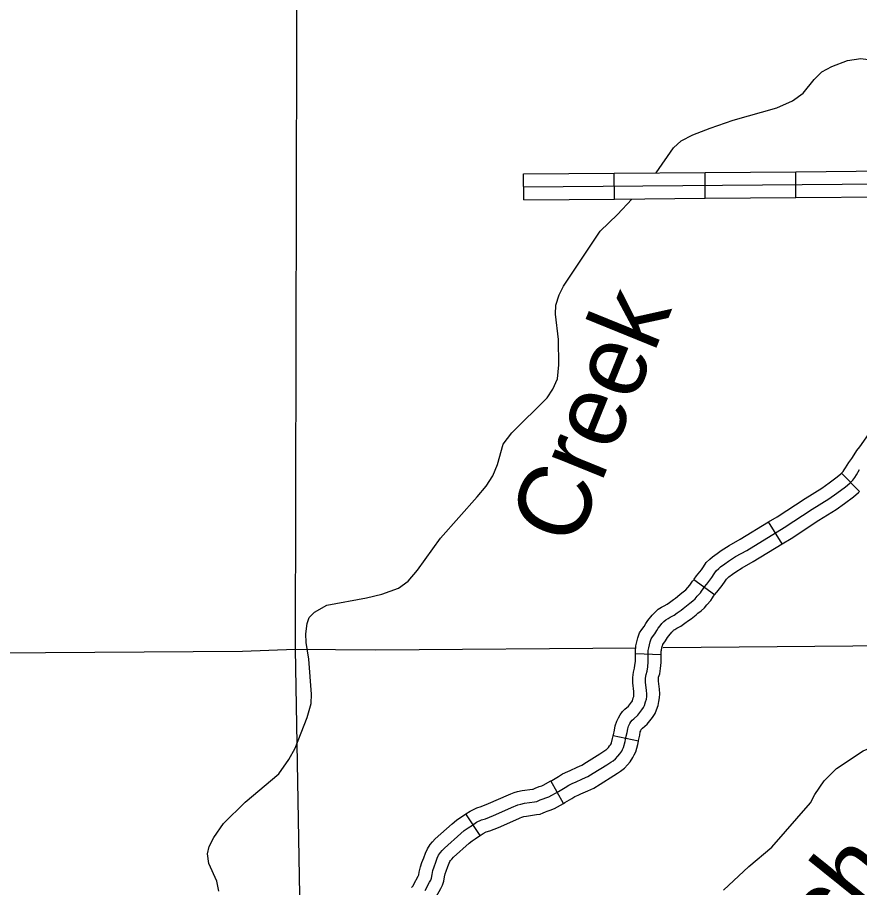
# Model space of a CAD drawing. Extents: x 1377389 to 1380723, y 1168351 to 1170484.
# Drawn here: x 1379286.7 to 1379384.7, y 1168808.8 to 1168910 of the extents above; entities that cross this region are included whole.
import ezdxf

# ---------------------------------------------------------------- set-up
doc = ezdxf.new("R2010")
doc.units = 0
doc.layers.add('B_Fill', color=7, linetype='Continuous')

msp = doc.modelspace()

# ---------------------------------------------------------------- linework, layer by layer
at = {"layer": 'B_Fill'}
for p, q in [((1379345.66, 1168888.81), (1379345.64, 1168891.81)), ((1379356.22, 1168888.89), (1379356.2, 1168891.89)), ((1379366.78, 1168888.98), (1379366.76, 1168891.98)), ((1379377.34, 1168889.07), (1379377.32, 1168892.07)), ((1379384.75, 1168854.89), (1379382.62, 1168857.01)), ((1379375.72, 1168848.78), (1379374.16, 1168851.34)), ((1379367.87, 1168842.86), (1379365.44, 1168844.62)), ((1379361.65, 1168835.89), (1379358.66, 1168836.01)), ((1379359, 1168825.85), (1379356.07, 1168826.46)), ((1379350.27, 1168818.59), (1379348.81, 1168821.21)), ((1379340.6, 1168814.88), (1379338.93, 1168817.37))]:
    msp.add_line(p, q, dxfattribs=at)
for points in [[(1379319.28, 1168942.2), (1379319.08, 1168836.54)], [(1379361.06, 1168891.95), (1379363.09, 1168894.85), (1379363.99, 1168895.67), (1379365.34, 1168896.37), (1379367.35, 1168897.12), (1379370.04, 1168898.06), (1379375.13, 1168899.52), (1379376.94, 1168900.3), (1379378.18, 1168901.2), (1379379.45, 1168902.78), (1379380.37, 1168903.7), (1379381.5, 1168904.33), (1379383.33, 1168905.01), (1379384.87, 1168905.24), (1379386.34, 1168905.04), (1379387.69, 1168905.62), (1379390.71, 1168908.37)], [(1379377.32, 1168892.07), (1379387.88, 1168892.16)], [(1379345.64, 1168891.81), (1379356.2, 1168891.89)], [(1379356.2, 1168891.89), (1379366.76, 1168891.98)], [(1379366.76, 1168891.98), (1379377.32, 1168892.07)], [(1379345.65, 1168890.31), (1379415.15, 1168890.89)], [(1379377.34, 1168889.07), (1379387.9, 1168889.16)], [(1379345.66, 1168888.81), (1379356.22, 1168888.89)], [(1379349.04, 1168866.78), (1379349.59, 1168868), (1379349.76, 1168869.6), (1379349.69, 1168872.54), (1379349.36, 1168875.49), (1379349.41, 1168876.56), (1379349.78, 1168877.75), (1379350.28, 1168878.78), (1379354.57, 1168885.14), (1379356.59, 1168887.09), (1379358.25, 1168888.89)], [(1379356.22, 1168888.89), (1379366.78, 1168888.98)], [(1379366.78, 1168888.98), (1379377.34, 1168889.07)], [(1379310.17, 1168808.39), (1379309.96, 1168809.57), (1379309.01, 1168811.61), (1379308.88, 1168812.73), (1379309.04, 1168813.58), (1379309.58, 1168814.62), (1379310.73, 1168816.25), (1379313.25, 1168818.73), (1379317.15, 1168822.05), (1379318.33, 1168823.7), (1379319.05, 1168825.02), (1379320.46, 1168828.59), (1379320.92, 1168830.23), (1379320.96, 1168831.29), (1379320.66, 1168835.37), (1379320.36, 1168837.3), (1379320.31, 1168838.34), (1379320.46, 1168839.53), (1379320.69, 1168840.22), (1379321.3, 1168840.85), (1379322.75, 1168841.64), (1379327.38, 1168842.5), (1379329.14, 1168842.92), (1379331.09, 1168843.62), (1379332.23, 1168844.45), (1379333.3, 1168845.72), (1379335.97, 1168849.45), (1379340.26, 1168854.25), (1379341.28, 1168855.51), (1379342.07, 1168856.71), (1379342.61, 1168858.02), (1379343.27, 1168860.37), (1379344.27, 1168861.72), (1379348.37, 1168865.77), (1379349.04, 1168866.78)], [(1379382.62, 1168857.01), (1379382.82, 1168857.21), (1379382.96, 1168857.38), (1379383.11, 1168857.63), (1379383.51, 1168858.26), (1379383.84, 1168858.72), (1379384.13, 1168859.16), (1379384.44, 1168859.63), (1379384.78, 1168860.07), (1379387.06, 1168863.34), (1379388.44, 1168865.44)], [(1379361.15, 1168838.72), (1379361.32, 1168838.98), (1379361.54, 1168839.25), (1379361.75, 1168839.51), (1379361.98, 1168839.75), (1379362.2, 1168839.97), (1379362.47, 1168840.11), (1379362.72, 1168840.27), (1379363.15, 1168840.49), (1379363.51, 1168840.76), (1379363.97, 1168841.09), (1379364.23, 1168841.28), (1379364.78, 1168841.72), (1379365, 1168841.9), (1379365.35, 1168842.16), (1379365.61, 1168842.41), (1379365.86, 1168842.69), (1379366.22, 1168843.08), (1379366.34, 1168843.3), (1379366.53, 1168843.56), (1379366.69, 1168843.79), (1379366.95, 1168844.11), (1379367.54, 1168844.86), (1379367.84, 1168845.29), (1379368.07, 1168845.65), (1379368.35, 1168845.92), (1379368.57, 1168846.12), (1379369.06, 1168846.47), (1379369.49, 1168846.79), (1379370.32, 1168847.3), (1379371.61, 1168848.03), (1379375.97, 1168850.69), (1379379.22, 1168852.82), (1379381.18, 1168854.01), (1379382.1, 1168854.68), (1379383.09, 1168855.41), (1379383.6, 1168855.86), (1379383.94, 1168856.21), (1379384.18, 1168856.51), (1379384.39, 1168856.83), (1379384.75, 1168857.42)], [(1379374.16, 1168851.34), (1379375.17, 1168851.95), (1379378.41, 1168854.08), (1379380.35, 1168855.26), (1379381.21, 1168855.89), (1379382.15, 1168856.58), (1379382.57, 1168856.95), (1379382.62, 1168857.01)], [(1379375.72, 1168848.78), (1379376.78, 1168849.42), (1379380.02, 1168851.55), (1379382.02, 1168852.77), (1379382.98, 1168853.47), (1379384.03, 1168854.24), (1379384.62, 1168854.77), (1379384.75, 1168854.89)], [(1379365.44, 1168844.62), (1379365.5, 1168844.7), (1379365.78, 1168845.05), (1379366.34, 1168845.76), (1379366.59, 1168846.12), (1379366.89, 1168846.61), (1379367.33, 1168847.02), (1379367.63, 1168847.29), (1379368.17, 1168847.67), (1379368.64, 1168848.03), (1379369.56, 1168848.59), (1379370.86, 1168849.32), (1379374.16, 1168851.34)], [(1379367.87, 1168842.86), (1379367.88, 1168842.87), (1379368.12, 1168843.18), (1379368.74, 1168843.96), (1379369.1, 1168844.46), (1379369.24, 1168844.7), (1379369.37, 1168844.81), (1379369.51, 1168844.95), (1379369.95, 1168845.26), (1379370.33, 1168845.55), (1379371.08, 1168846), (1379372.37, 1168846.73), (1379375.72, 1168848.78)], [(1379358.66, 1168836.01), (1379358.66, 1168836.06), (1379358.66, 1168836.5), (1379358.72, 1168836.94), (1379358.82, 1168837.4), (1379358.94, 1168837.86), (1379359.15, 1168838.44), (1379359.42, 1168838.83), (1379359.66, 1168839.16), (1379359.88, 1168839.53), (1379360.11, 1168839.87), (1379360.62, 1168840.5), (1379360.92, 1168840.81), (1379361.31, 1168841.19), (1379361.71, 1168841.41), (1379361.99, 1168841.58), (1379362.36, 1168841.77), (1379362.62, 1168841.96), (1379363.09, 1168842.31), (1379363.33, 1168842.48), (1379363.84, 1168842.88), (1379364.07, 1168843.08), (1379364.38, 1168843.31), (1379364.53, 1168843.45), (1379364.74, 1168843.7), (1379365, 1168843.97), (1379365.06, 1168844.09), (1379365.3, 1168844.43), (1379365.44, 1168844.62)], [(1379368.91, 1168808.52), (1379371.87, 1168811.26), (1379374.55, 1168813.52), (1379379.02, 1168818.66), (1379379.55, 1168819.63), (1379380.64, 1168821.22), (1379382.06, 1168822.67), (1379385.15, 1168824.71), (1379387.5, 1168825.69), (1379389.38, 1168826.09), (1379395.47, 1168825.84), (1379400.06, 1168825.42), (1379401.05, 1168825.58), (1379401.74, 1168825.89), (1379402.06, 1168826.26), (1379402.69, 1168827.8), (1379403.18, 1168830.02), (1379403.74, 1168831.65), (1379404.6, 1168833.21), (1379406.14, 1168834.84), (1379408.31, 1168836.36), (1379416.83, 1168840.28), (1379419.61, 1168841.74), (1379421.82, 1168843.62)], [(1379361.65, 1168835.89), (1379361.66, 1168836.01), (1379361.66, 1168836.29), (1379361.68, 1168836.41), (1379361.74, 1168836.71), (1379361.81, 1168836.97), (1379361.84, 1168837.06), (1379361.86, 1168837.09), (1379362.16, 1168837.49), (1379362.41, 1168837.91), (1379362.53, 1168838.09), (1379362.88, 1168838.53), (1379363.04, 1168838.69), (1379363.09, 1168838.75), (1379363.23, 1168838.82), (1379363.46, 1168838.97), (1379363.94, 1168839.21), (1379364.4, 1168839.55), (1379364.84, 1168839.87), (1379365.13, 1168840.08), (1379365.73, 1168840.55), (1379365.94, 1168840.72), (1379366.32, 1168841.01), (1379366.7, 1168841.36), (1379366.97, 1168841.69), (1379367.44, 1168842.19), (1379367.62, 1168842.51), (1379367.75, 1168842.7), (1379367.87, 1168842.86)], [(1379334.18, 1168808.46), (1379334.71, 1168809.44), (1379334.84, 1168809.68), (1379334.92, 1168809.92), (1379334.99, 1168810.33), (1379335.08, 1168810.81), (1379335.23, 1168811.22), (1379335.43, 1168811.76), (1379335.6, 1168812.24), (1379335.76, 1168812.58), (1379335.96, 1168812.87), (1379336.18, 1168813.11), (1379336.43, 1168813.4), (1379338.34, 1168815.11), (1379338.74, 1168815.45), (1379339.18, 1168815.75), (1379339.7, 1168816.08), (1379340.18, 1168816.4), (1379340.76, 1168816.68), (1379341.21, 1168816.82), (1379342.15, 1168817.19), (1379344.5, 1168818.24), (1379344.71, 1168818.33), (1379344.98, 1168818.42), (1379345.31, 1168818.52), (1379345.74, 1168818.61), (1379346.92, 1168818.77), (1379347.17, 1168818.81), (1379347.33, 1168818.88), (1379347.59, 1168819), (1379347.92, 1168819.13), (1379348.25, 1168819.23), (1379348.57, 1168819.36), (1379349.7, 1168819.99), (1379350.47, 1168820.46), (1379350.9, 1168820.72), (1379351.38, 1168820.94), (1379351.69, 1168821.07), (1379352.49, 1168821.45), (1379353.13, 1168821.73), (1379353.76, 1168822.11), (1379355.32, 1168823.1), (1379355.79, 1168823.41), (1379356.07, 1168823.57), (1379356.34, 1168823.79), (1379356.63, 1168824.11), (1379356.86, 1168824.36), (1379357.06, 1168824.67), (1379357.17, 1168824.88), (1379357.27, 1168825.11), (1379357.46, 1168825.79), (1379357.55, 1168826.25), (1379357.7, 1168826.84), (1379357.77, 1168827.26), (1379357.87, 1168827.6), (1379358.01, 1168827.88), (1379358.11, 1168828.07), (1379358.27, 1168828.27), (1379358.46, 1168828.45), (1379358.93, 1168828.87), (1379359.42, 1168829.47), (1379359.6, 1168829.74), (1379359.7, 1168830), (1379359.85, 1168830.43), (1379359.93, 1168830.74), (1379359.97, 1168831.02), (1379359.99, 1168831.33), (1379359.96, 1168831.74), (1379359.85, 1168832.72), (1379359.84, 1168833.17), (1379359.89, 1168833.58), (1379360.01, 1168833.99), (1379360.09, 1168834.48), (1379360.15, 1168835.05), (1379360.15, 1168835.34), (1379360.15, 1168835.69), (1379360.16, 1168836.04), (1379360.16, 1168836.4), (1379360.2, 1168836.68), (1379360.28, 1168837.05), (1379360.37, 1168837.41), (1379360.49, 1168837.75), (1379360.64, 1168837.96), (1379360.91, 1168838.32), (1379361.15, 1168838.72)], [(1379215.55, 1168835.63), (1379312.94, 1168836.32), (1379319.08, 1168836.54)], [(1379319.08, 1168836.54), (1379328.46, 1168836.45), (1379358.76, 1168836.71)], [(1379319.08, 1168836.54), (1379320.39, 1168761.67)], [(1379361.88, 1168836.73), (1379423.73, 1168837.26)], [(1379356.07, 1168826.46), (1379356.09, 1168826.58), (1379356.23, 1168827.13), (1379356.3, 1168827.61), (1379356.48, 1168828.15), (1379356.68, 1168828.57), (1379356.87, 1168828.91), (1379357.16, 1168829.27), (1379357.43, 1168829.55), (1379357.85, 1168829.91), (1379358.21, 1168830.36), (1379358.26, 1168830.43), (1379358.3, 1168830.53), (1379358.41, 1168830.87), (1379358.46, 1168831.04), (1379358.48, 1168831.16), (1379358.48, 1168831.31), (1379358.46, 1168831.61), (1379358.35, 1168832.62), (1379358.34, 1168833.25), (1379358.42, 1168833.88), (1379358.55, 1168834.32), (1379358.6, 1168834.68), (1379358.65, 1168835.12), (1379358.65, 1168835.34), (1379358.65, 1168835.72), (1379358.66, 1168836.01)], [(1379359, 1168825.85), (1379359.02, 1168825.91), (1379359.17, 1168826.54), (1379359.23, 1168826.92), (1379359.27, 1168827.04), (1379359.34, 1168827.18), (1379359.36, 1168827.22), (1379359.39, 1168827.26), (1379359.49, 1168827.36), (1379360.01, 1168827.82), (1379360.64, 1168828.58), (1379360.94, 1168829.04), (1379361.11, 1168829.48), (1379361.29, 1168830), (1379361.4, 1168830.44), (1379361.47, 1168830.88), (1379361.49, 1168831.34), (1379361.45, 1168831.87), (1379361.35, 1168832.82), (1379361.34, 1168833.1), (1379361.36, 1168833.27), (1379361.48, 1168833.66), (1379361.58, 1168834.29), (1379361.65, 1168834.97), (1379361.65, 1168835.34), (1379361.65, 1168835.66), (1379361.65, 1168835.89)], [(1379348.81, 1168821.21), (1379348.94, 1168821.28), (1379349.69, 1168821.73), (1379350.19, 1168822.05), (1379350.78, 1168822.31), (1379351.07, 1168822.44), (1379351.87, 1168822.81), (1379352.43, 1168823.06), (1379352.96, 1168823.39), (1379354.51, 1168824.36), (1379355, 1168824.69), (1379355.22, 1168824.82), (1379355.31, 1168824.88), (1379355.52, 1168825.11), (1379355.66, 1168825.28), (1379355.76, 1168825.42), (1379355.82, 1168825.54), (1379355.86, 1168825.63), (1379356, 1168826.14), (1379356.07, 1168826.46)], [(1379350.27, 1168818.59), (1379350.45, 1168818.69), (1379351.26, 1168819.18), (1379351.61, 1168819.4), (1379351.98, 1168819.56), (1379352.3, 1168819.7), (1379353.11, 1168820.08), (1379353.83, 1168820.39), (1379354.55, 1168820.84), (1379356.14, 1168821.84), (1379356.57, 1168822.13), (1379356.92, 1168822.33), (1379357.37, 1168822.69), (1379357.74, 1168823.1), (1379358.05, 1168823.45), (1379358.36, 1168823.92), (1379358.52, 1168824.23), (1379358.69, 1168824.59), (1379358.92, 1168825.44), (1379359, 1168825.85)], [(1379338.93, 1168817.37), (1379339.43, 1168817.71), (1379340.21, 1168818.09), (1379340.72, 1168818.24), (1379341.56, 1168818.58), (1379343.89, 1168819.61), (1379344.16, 1168819.73), (1379344.53, 1168819.85), (1379344.95, 1168819.97), (1379345.48, 1168820.09), (1379346.7, 1168820.26), (1379346.75, 1168820.26), (1379346.99, 1168820.37), (1379347.44, 1168820.55), (1379347.76, 1168820.65), (1379347.92, 1168820.71), (1379348.81, 1168821.21)], [(1379340.6, 1168814.88), (1379340.93, 1168815.1), (1379341.3, 1168815.28), (1379341.7, 1168815.4), (1379342.73, 1168815.81), (1379345.1, 1168816.86), (1379345.26, 1168816.93), (1379345.43, 1168816.99), (1379345.68, 1168817.06), (1379346, 1168817.13), (1379347.14, 1168817.29), (1379347.58, 1168817.36), (1379347.94, 1168817.51), (1379348.19, 1168817.62), (1379348.4, 1168817.71), (1379348.75, 1168817.81), (1379349.23, 1168818.01), (1379350.27, 1168818.59)], [(1379332.6, 1168808.81), (1379332.68, 1168808.91), (1379332.78, 1168809.03), (1379332.88, 1168809.2), (1379333.39, 1168810.15), (1379333.46, 1168810.28), (1379333.51, 1168810.6), (1379333.63, 1168811.22), (1379333.82, 1168811.73), (1379334.02, 1168812.28), (1379334.22, 1168812.83), (1379334.46, 1168813.33), (1379334.78, 1168813.8), (1379335.06, 1168814.12), (1379335.37, 1168814.46), (1379337.35, 1168816.23), (1379337.83, 1168816.65), (1379338.36, 1168817), (1379338.88, 1168817.34), (1379338.93, 1168817.37)], [(1379334.91, 1168806.9), (1379335.04, 1168807.05), (1379335.27, 1168807.36), (1379335.49, 1168807.72), (1379336.02, 1168808.72), (1379336.22, 1168809.07), (1379336.38, 1168809.56), (1379336.46, 1168810.07), (1379336.53, 1168810.41), (1379336.64, 1168810.7), (1379336.84, 1168811.25), (1379336.99, 1168811.66), (1379337.06, 1168811.83), (1379337.15, 1168811.95), (1379337.29, 1168812.11), (1379337.49, 1168812.33), (1379339.33, 1168813.98), (1379339.65, 1168814.26), (1379340, 1168814.49), (1379340.52, 1168814.83), (1379340.6, 1168814.88)]]:
    msp.add_lwpolyline(points, dxfattribs=at)

# ---------------------------------------------------------------- texts
for s, rotation, p in [('Creek', 67.8916, (1379351.6, 1168848.21)), ('Branch', 51.2188, (1379366.74, 1168782.8))]:
    msp.add_text(s, height=8.448, rotation=rotation, dxfattribs=at).set_placement(p)

doc.saveas('drawing.dxf')
